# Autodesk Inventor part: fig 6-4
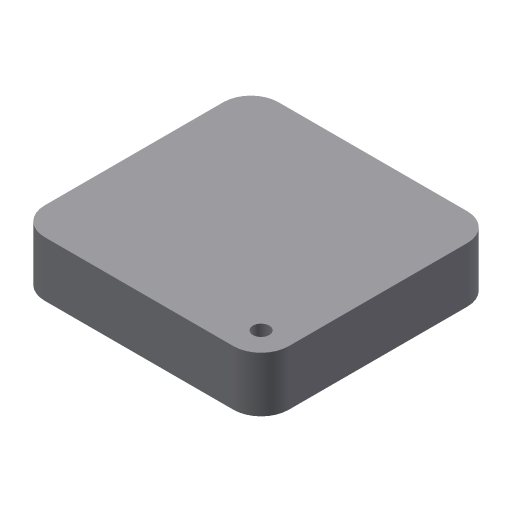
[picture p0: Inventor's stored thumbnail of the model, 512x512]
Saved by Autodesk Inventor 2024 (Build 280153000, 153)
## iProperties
Created: 2004-05
Part Number: fig 6-4
Document SubType Name: Modeling
Designer: CADCIM Technologies
Manufacturer: Standard
Standards Organization: Custom
Density: 1 g/cm^3
Material: Generic
Appearance: Default
Author: CADCIM Technologies
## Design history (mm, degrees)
sketch "Sketch1"
  geometry: L1 (0, 0)-(44.293, 0); L2 (44.293, 0)-(44.293, 42.442); L3 (44.293, 42.442)-(0, 42.442); L4 (0, 42.442)-(0, 0)
  constraints: 8 end point, 2 parallel, 1 horizontal, 1 perpendicular
extrude "Extrusion1" new body sketch "Sketch1" distance "d0" = 10; taper "d1" = 0 deg
fillet "Fillet1" dims "d2" = 5
sketch "Sketch2"
  geometry: 1 further point
sketch "Sketch3"
  geometry: L1 (5, 42.442)-(39.293, 42.442) reference; L2 (0, 5)-(0, 37.442) reference; L3 (39.293, 0)-(5, 0) reference; L4 (44.293, 37.442)-(44.293, 5) reference; A1 r 5 centre (39.293, 37.442) between (44.293, 37.442) and (39.293, 42.442) reference; A2 r 5 centre (5, 37.442) between (5, 42.442) and (0, 37.442) reference; A3 r 5 centre (5, 5) between (0, 5) and (5, 0) reference; A4 r 5 centre (39.293, 5) between (39.293, 0) and (44.293, 5) reference; 1 further point
hole "Hole2" diameter "d15" = 3; stored, may be unused: countersink angle "d19" = 90 deg, drill point angle "d21" = 118 deg; dims "d13" = 10, "d14" = 10, "d16" = 6, "d17" = 4, "d18" = 2, "d20" = 8
body "Solid1"
